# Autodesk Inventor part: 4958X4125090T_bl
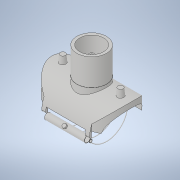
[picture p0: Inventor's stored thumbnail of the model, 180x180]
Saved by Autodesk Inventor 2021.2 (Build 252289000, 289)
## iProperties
Created: 2020-06
Part Number: 4958X4125090T_bl
Material: Generic
Description: Plasson Branch Saddle 125x90
Document SubType Name: Modeling
Designer: KIM
Density: 1 g/cm^3
Appearance: Default
Author: KIM
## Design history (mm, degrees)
derived "4958X4.ipt"
feature "Solid1::4958X4.ipt" dims "ScaleForDerivedMember" = 10
tag "TaggingFeature1"
body "Solid1"
other parameters: "d" = 125 [user parameter], "L" = 242 [user parameter], "LS" = 81 [user parameter], "H1" = 106 [user parameter], "Dt" = 16 [user parameter], "di" = 73 [user parameter], "d72" = 16.5 [user parameter], "d0" = 242 [user parameter], "d2" = 125 [user parameter], "d3" = 158 [user parameter], "d4" = 106 [user parameter], "d7" = 73 [user parameter], "d9" = 81 [user parameter], "d10" = 0.5 [user parameter], "d11" = 1 [user parameter], "d12" = 26.5 [user parameter], "d13" = 16 [user parameter], "d14" = 8 [user parameter], "d16" = 10 deg [user parameter], "d17" = 10 deg [user parameter], "d19" = 0 [user parameter], "d23" = 0 [user parameter], "d26" = 0 [user parameter], "d27" = 145.2 [user parameter], "d28" = 0 [user parameter], "d29" = 121 [user parameter], "d30" = 0 [user parameter], "d31" = 1 [user parameter], "d32" = 1 [user parameter], "d33" = 19.2 [user parameter], "d34" = 9.6 [user parameter], "d35" = 45 deg [user parameter], "d36" = 121 [user parameter], "d37" = 0 [user parameter], "d38" = 5 [user parameter], "d39" = 85 deg [user parameter], "d40" = 26.5 [user parameter], "d41" = 16 [user parameter], "d42" = 88 [user parameter], "d49" = 3 [user parameter], "d50" = 6 [user parameter], "d51" = 5 [user parameter], "d54" = 0 [user parameter], "d57" = 35 deg [user parameter], "d60" = 15.125 [user parameter], "d61" = 1 [user parameter], "d62" = 90 deg [user parameter], "d63" = 2 [user parameter], "d64" = 0 [user parameter], "d65" = 0 [user parameter], "d68" = 30.25 [user parameter], "d70" = 0.57711 [user parameter], "d71" = 10 deg [user parameter], "d73" = 5.775 [user parameter]
